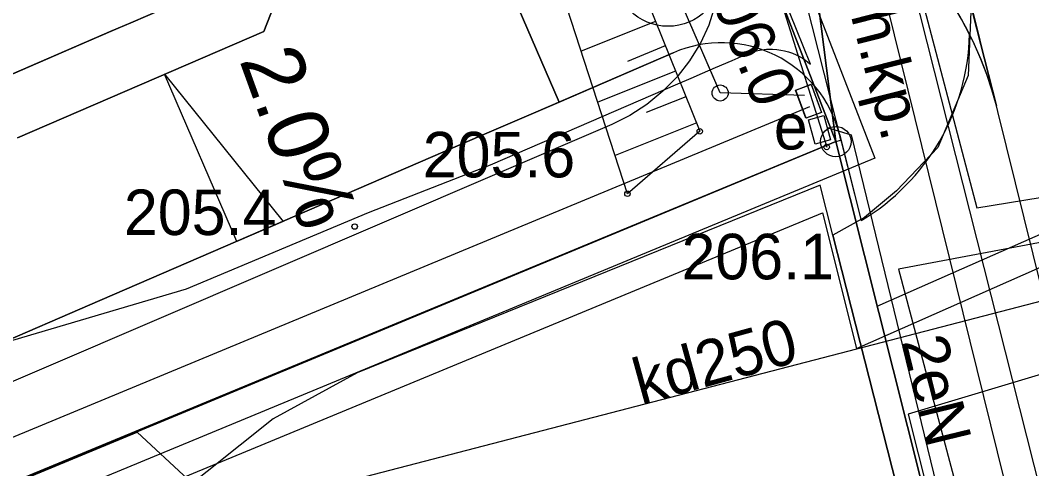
# Model space of a CAD drawing. Extents: x 6512606 to 6513006, y 6022524 to 6022728.
# Drawn here: x 6512842.35 to 6512859.01, y 6022578.56 to 6022585.95 of the extents above; entities that cross this region are included whole.
import ezdxf

# ---------------------------------------------------------------- set-up
doc = ezdxf.new("R2010")
doc.units = 0
for name, color, linetype in [('000 Inne (niezydentyfikowane)', 7, 'Continuous'), ('202-punkt graniczny', 7, 'Continuous'), ('216-obręb ewidencyjny', 7, 'Continuous'), ('217-kontur klasyfikacyjny', 7, 'Continuous'), ('218-kontur użytku gruntowego', 7, 'Continuous'), ('219-działka ewidencyjna', 7, 'Continuous'), ('4', 7, 'Continuous'), ('chodnik (powierzchnia)', 7, 'Continuous'), ('chodnik (powierzchnia)-Atr17', 7, 'Continuous'), ('Default', 7, 'Continuous'), ('E_OSW_KABLE', 7, 'Continuous'), ('E_OSW_LAMPA', 7, 'Continuous'), ('jezdnia (powierzchnia)', 7, 'Continuous'), ('kolor_chodnik', 7, 'Continuous'), ('kolor_kostka_bet', 7, 'Continuous'), ('kolor_sc_rowerowa', 7, 'Continuous'), ('maxp_inst_energ', 7, 'Continuous'), ('maxp_kan_deszczowa', 7, 'Continuous'), ('maxp_kraw_nawierzchni', 7, 'Continuous'), ('maxp_krawężnik', 7, 'Continuous'), ('maxp_obrzeże', 7, 'Continuous'), ('maxp_przechyłki', 7, 'Continuous'), ('maxp_ramka_2', 7, 'Continuous'), ('ogrodzenie trwałe', 7, 'Continuous'), ('pikieta naturalna', 7, 'Continuous'), ('pikieta naturalna-Atr2', 7, 'Continuous'), ('przewód elektroenergetyczny (linia)', 7, 'Continuous'), ('przewód elektroenergetyczny (linia)-Atr1', 7, 'Continuous'), ('przewód kanalizacyjny (linia)', 7, 'Continuous'), ('przewód kanalizacyjny (linia)-Atr1', 7, 'Continuous'), ('przewód telekomunikacyjny (linia)', 7, 'Continuous'), ('skarpa nieumocniona', 7, 'Continuous'), ('szafa elektroenergetyczna (powierzchnia)', 7, 'Continuous'), ('szafa elektroenergetyczna (powierzchnia)-Atr17', 7, 'Continuous'), ('urządzenie techniczne projektowane lub w budowie (sieć kanalizacyjna) - powierzchnia - ob. projektowany', 7, 'Continuous')]:
    doc.layers.add(name, color=color, linetype=linetype)

# ---------------------------------------------------------------- blocks, each defined once
blk = doc.blocks.new('202')
at = {"layer": 'Default'}
blk.add_circle((0, 0), 2.5, dxfattribs=at)
blk = doc.blocks.new('PW01')
at = {"layer": 'Default'}
blk.add_circle((0, 0), 0.45, dxfattribs=at)

msp = doc.modelspace()

# ---------------------------------------------------------------- linework, layer by layer
at = {"layer": '000 Inne (niezydentyfikowane)'}
for points in [[(6512852.81, 6022585.93), (6512851.59, 6022585.44)], [(6512852.97, 6022585.53), (6512852.35, 6022585.27)], [(6512853.14, 6022585.11), (6512851.86, 6022584.6)], [(6512853.31, 6022584.69), (6512852.66, 6022584.43)], [(6512853.49, 6022584.26), (6512852.15, 6022583.72)]]:
    msp.add_lwpolyline(points, dxfattribs=at)
at = {"layer": '216-obręb ewidencyjny'}
for points in [[(6512836.687, 6022675.173), (6512833.61, 6022675.02), (6512828.67, 6022670.98), (6512801.96, 6022670.34), (6512810.18, 6022663.28), (6512825.37, 6022649.66), (6512838.47, 6022634.29), (6512852.25, 6022608.25), (6512853.17, 6022604.51), (6512855.78, 6022583.95), (6512858.85, 6022571.74), (6512828.23, 6022562.62), (6512818.47, 6022559.72), (6512824.714, 6022553.406)], [(6512728.286, 6022540.131), (6512737.69, 6022552.74), (6512751.08, 6022569.37), (6512775.81, 6022564.08), (6512780.7, 6022581.02), (6512806.2, 6022572.11), (6512806.62, 6022563.51), (6512811.41, 6022558.95), (6512818.47, 6022559.72), (6512828.23, 6022562.62), (6512858.85, 6022571.74), (6512855.78, 6022583.95), (6512853.17, 6022604.51), (6512852.25, 6022608.25), (6512838.47, 6022634.29)]]:
    msp.add_lwpolyline(points, dxfattribs=at)
at = {"layer": '217-kontur klasyfikacyjny'}
for points in [[(6512855.78, 6022583.95), (6512848.55, 6022602.62)], [(6512825.22, 6022571.29), (6512855.78, 6022583.95)]]:
    msp.add_lwpolyline(points, dxfattribs=at)
at = {"layer": '218-kontur użytku gruntowego'}
for points in [[(6512855.78, 6022583.95), (6512853.17, 6022604.51)], [(6512853.17, 6022604.51), (6512855.78, 6022583.95)], [(6512848.55, 6022602.62), (6512855.78, 6022583.95)], [(6512855.78, 6022583.95), (6512848.55, 6022602.62)], [(6512825.22, 6022571.29), (6512855.78, 6022583.95)], [(6512855.78, 6022583.95), (6512825.22, 6022571.29)], [(6512858.85, 6022571.74), (6512855.78, 6022583.95)], [(6512855.78, 6022583.95), (6512858.85, 6022571.74)]]:
    msp.add_lwpolyline(points, dxfattribs=at)
at = {"layer": '219-działka ewidencyjna'}
for points in [[(6512855.78, 6022583.95), (6512853.17, 6022604.51)], [(6512855.78, 6022583.95), (6512848.55, 6022602.62)], [(6512825.22, 6022571.29), (6512855.78, 6022583.95)], [(6512858.85, 6022571.74), (6512855.78, 6022583.95)]]:
    msp.add_lwpolyline(points, dxfattribs=at)
at = {"layer": '4'}
for points in [[(6512855.78, 6022583.95), (6512853.17, 6022604.51)], [(6512855.78, 6022583.95), (6512848.55, 6022602.62)], [(6512825.22, 6022571.29), (6512855.78, 6022583.95)], [(6512858.85, 6022571.74), (6512855.78, 6022583.95)]]:
    msp.add_lwpolyline(points, dxfattribs=at)
at = {"layer": 'chodnik (powierzchnia)'}
msp.add_lwpolyline([(6512854.31, 6022590.11), (6512856.17, 6022582.76)], dxfattribs=at)
at = {"layer": 'E_OSW_KABLE'}
msp.add_lwpolyline([(6512855.264, 6022584.708), (6512853.876, 6022584.751), (6512849.902, 6022593.935)], dxfattribs=at)
for points in [[(6512855.117, 6022584.799), (6512855.373, 6022584.893), (6512855.544, 6022584.431), (6512855.289, 6022584.335)], [(6512855.119, 6022584.8), (6512855.374, 6022584.894), (6512855.545, 6022584.431), (6512855.291, 6022584.336)]]:
    msp.add_lwpolyline(points, close=True, dxfattribs=at)
at = {"layer": 'E_OSW_LAMPA'}
msp.add_line((6512853.372, 6022585.915), (6512853.823, 6022584.872), dxfattribs=at)
for centre, radius in [((6512853.018, 6022586.735), 0.885), ((6512853.876, 6022584.751), 0.132)]:
    msp.add_circle(centre, radius, dxfattribs=at)
at = {"layer": 'jezdnia (powierzchnia)'}
for points in [[(6512858.01, 6022586.22), (6512857.96, 6022585.04), (6512857.46, 6022583.85), (6512856.78, 6022583.14), (6512856.25, 6022582.7), (6512855.73, 6022582.41), (6512857.16, 6022576.8), (6512857.52, 6022576.87), (6512858.5, 6022576.75), (6512859.52, 6022576.13), (6512860.31, 6022575.24), (6512860.92, 6022574.44)], [(6512857.37, 6022576.01), (6512857.16, 6022576.8), (6512855.73, 6022582.41), (6512855.52, 6022583.23), (6512847.9, 6022580.14), (6512846.52, 6022579.38), (6512844.89, 6022578.08), (6512844.32, 6022577.3), (6512843.83, 6022576.12), (6512843.75, 6022575.7), (6512844.49, 6022572.59), (6512851.42, 6022574.26), (6512851.6, 6022573.59), (6512851.75, 6022573.46), (6512852.45, 6022574.3), (6512853.58, 6022574.86), (6512856.56, 6022575.84)]]:
    msp.add_lwpolyline(points, close=True, dxfattribs=at)
at = {"layer": 'kolor_chodnik'}
for p, q in [((6512849.637, 6022588.273), (6512851.225, 6022584.602)), ((6512851.225, 6022584.602), (6512853.105, 6022585.415))]:
    msp.add_line(p, q, dxfattribs=at)
msp.add_lwpolyline([(6512855.838, 6022584.07), (6512855.864, 6022583.971), (6512856.198, 6022582.648)], dxfattribs=at)
for centre, radius, start, end in [((6512852.619, 6022583.025), 6, 26.6607, 48.1262), ((6512854.308, 6022585.798), 3.674, 300.9641, 358.7377), ((6512853.9, 6022583.579), 2, 14.2012, 113.397)]:
    msp.add_arc(centre, radius, start, end, dxfattribs=at)
at = {"layer": 'kolor_kostka_bet'}
for p, q in [((6512858.424, 6022584.541), (6512854.975, 6022598.118)), ((6512844.176, 6022585.91), (6512848.334, 6022587.709)), ((6512846.363, 6022585.766), (6512846.884, 6022587.081)), ((6512841.472, 6022584.74), (6512843.862, 6022585.774)), ((6512842.307, 6022584.011), (6512846.363, 6022585.766)), ((6512843.862, 6022585.774), (6512844.176, 6022585.91)), ((6512849.922, 6022584.038), (6512843.498, 6022581.258)), ((6512855.864, 6022583.971), (6512855.838, 6022584.07)), ((6512843.498, 6022581.258), (6512839.274, 6022579.431))]:
    msp.add_line(p, q, dxfattribs=at)
for points in [[(6512846.884, 6022587.081), (6512844.176, 6022585.91), (6512843.862, 6022585.774)], [(6512843.862, 6022585.774), (6512841.909, 6022584.929), (6512841.472, 6022584.74)], [(6512853.105, 6022585.415), (6512851.225, 6022584.602), (6512849.922, 6022584.038)], [(6512773.05, 6022582.65), (6512780.7, 6022581.02), (6512806.2, 6022572.11), (6512806.62, 6022563.51), (6512855.78, 6022583.95)], [(6512773.05, 6022582.65), (6512780.7, 6022581.02), (6512806.2, 6022572.11), (6512806.62, 6022563.51), (6512855.78, 6022583.95)], [(6512855.78, 6022583.95), (6512855.864, 6022583.971)]]:
    msp.add_lwpolyline(points, dxfattribs=at)
for centre, radius, start in [((6512852.619, 6022583.025), 6, 14.633), ((6512853.9, 6022583.579), 2, 14.2012)]:
    msp.add_arc(centre, radius, start, 113.397, dxfattribs=at)
at = {"layer": 'kolor_sc_rowerowa'}
for p, q in [((6512851.225, 6022584.602), (6512849.637, 6022588.273)), ((6512846.884, 6022587.081), (6512846.363, 6022585.766)), ((6512846.363, 6022585.766), (6512842.307, 6022584.011)), ((6512849.922, 6022584.038), (6512851.225, 6022584.602)), ((6512843.498, 6022581.258), (6512849.922, 6022584.038)), ((6512839.274, 6022579.431), (6512843.498, 6022581.258))]:
    msp.add_line(p, q, dxfattribs=at)
at = {"layer": 'maxp_inst_energ'}
msp.add_line((6512828.214, 6022573.256), (6512855.354, 6022584.531), dxfattribs=at)
at = {"layer": 'maxp_kan_deszczowa'}
msp.add_lwpolyline([(6512841.985, 6022580.604), (6512845.089, 6022581.521), (6512848.087, 6022582.782), (6512848.087, 6022582.782), (6512850.094, 6022583.567), (6512851.554, 6022584.199), (6512852.937, 6022584.797), (6512852.937, 6022584.797), (6512853.18, 6022584.902), (6512853.396, 6022584.996), (6512853.585, 6022585.078), (6512853.801, 6022585.171), (6512854.071, 6022585.288), (6512854.322, 6022585.397), (6512854.372, 6022585.416), (6512854.423, 6022585.432), (6512854.475, 6022585.446), (6512854.521, 6022585.456), (6512854.559, 6022585.462), (6512854.638, 6022585.471), (6512854.686, 6022585.473), (6512854.738, 6022585.472), (6512854.81, 6022585.467), (6512854.875, 6022585.458), (6512854.936, 6022585.446), (6512855.002, 6022585.428), (6512855.066, 6022585.405), (6512855.126, 6022585.38), (6512855.192, 6022585.346), (6512855.23, 6022585.324), (6512855.282, 6022585.29), (6512855.321, 6022585.261), (6512855.362, 6022585.227), (6512855.131, 6022585.797), (6512853.495, 6022589.851)], dxfattribs=at)
at = {"layer": 'maxp_kraw_nawierzchni'}
msp.add_line((6512851.225, 6022584.602), (6512849.637, 6022588.273), dxfattribs=at)
at = {"layer": 'maxp_krawężnik'}
msp.add_line((6512846.884, 6022587.081), (6512841.909, 6022584.929), dxfattribs=at)
msp.add_arc((6512852.619, 6022583.025), 6, 14.633, 94.6616, dxfattribs=at)
at = {"layer": 'maxp_obrzeże'}
for p, q in [((6512854.975, 6022598.118), (6512858.424, 6022584.541)), ((6512846.363, 6022585.766), (6512846.884, 6022587.081)), ((6512846.363, 6022585.766), (6512842.307, 6022584.011)), ((6512853.105, 6022585.415), (6512843.498, 6022581.258)), ((6512855.838, 6022584.07), (6512856.198, 6022582.648)), ((6512843.498, 6022581.258), (6512839.274, 6022579.43))]:
    msp.add_line(p, q, dxfattribs=at)
for centre, radius, start, end in [((6512854.308, 6022585.798), 3.674, 300.9641, 358.7377), ((6512853.9, 6022583.579), 2, 14.2012, 113.397)]:
    msp.add_arc(centre, radius, start, end, dxfattribs=at)
at = {"layer": 'maxp_przechyłki'}
msp.add_lwpolyline([(6512844.727, 6022585.062), (6512846.68, 6022582.635), (6512845.92, 6022582.304)], close=True, dxfattribs=at)
at = {"layer": 'maxp_ramka_2'}
for p, q in [((6512848.827, 6022603.29), (6512856.423, 6022583.675)), ((6512855.903, 6022583.46), (6512856.462, 6022581.237)), ((6512855.56, 6022582.776), (6512856.122, 6022580.54)), ((6512856.462, 6022581.237), (6512860.068, 6022582.835)), ((6512856.122, 6022580.54), (6512860.654, 6022582.548))]:
    msp.add_line(p, q, dxfattribs=at)
for points in [[(6512856.423, 6022583.675), (6512826.273, 6022571.185), (6512822.563, 6022569.637), (6512806.155, 6022562.774)], [(6512805.691, 6022562.037), (6512822.756, 6022569.175), (6512826.465, 6022570.723), (6512855.56, 6022582.776)]]:
    msp.add_lwpolyline(points, dxfattribs=at)
at = {"layer": 'ogrodzenie trwałe'}
for points in [[(6512853.88, 6022589.44), (6512855.63, 6022583.86)], [(6512818.46, 6022560.27), (6512812.53, 6022565.9), (6512821.8, 6022569.74), (6512835.02, 6022575.32), (6512844.28, 6022579.16), (6512845.12, 6022578.38)]]:
    msp.add_lwpolyline(points, dxfattribs=at)
at = {"layer": 'przewód elektroenergetyczny (linia)'}
for points in [[(6512802.27, 6022673.66), (6512807.42, 6022670.09), (6512811.38, 6022666.87), (6512814.66, 6022663.43), (6512826.4, 6022651.65), (6512827.82, 6022650.09), (6512834.03, 6022642.46), (6512842.84, 6022631.19), (6512844.67, 6022626.95), (6512847.57, 6022619.87), (6512849.81, 6022612.67), (6512853.56, 6022600.08), (6512856.46, 6022588.83), (6512861.26, 6022569.82), (6512861.768, 6022567.654)], [(6512847.6, 6022616.23), (6512852.12, 6022605.09), (6512853.39, 6022601.13), (6512855.57, 6022592.48), (6512858.1, 6022582.86), (6512868.09, 6022584.49), (6512870.03, 6022584.23), (6512871.36, 6022584.34), (6512875.65, 6022585.56)], [(6512861.56, 6022603.29), (6512861.94, 6022603.39), (6512866.18, 6022583.61), (6512856.81, 6022581.85), (6512858.91, 6022573.95), (6512860.571, 6022567.194)], [(6512881.03, 6022586.32), (6512872.09, 6022583.77), (6512862.68, 6022581.17), (6512856.97, 6022579.46), (6512860.103, 6022567.013)], [(6512855.64, 6022584.18), (6512856.03, 6022584.06), (6512858.14, 6022575.39), (6512858.48, 6022574.45)], [(6512866.18, 6022583.61), (6512856.81, 6022581.85), (6512858.91, 6022573.95), (6512860.571, 6022567.194)]]:
    msp.add_lwpolyline(points, dxfattribs=at)
at = {"layer": 'przewód kanalizacyjny (linia)'}
msp.add_lwpolyline([(6512840.49, 6022576.47), (6512866.73, 6022583.29)], dxfattribs=at)
at = {"layer": 'przewód telekomunikacyjny (linia)'}
msp.add_lwpolyline([(6512836.6, 6022638.32), (6512844.42, 6022625.21), (6512848.91, 6022613.6), (6512851.86, 6022605.02), (6512853.91, 6022597.19), (6512860.14, 6022571.94), (6512860.33, 6022571.18)], dxfattribs=at)
at = {"layer": 'skarpa nieumocniona'}
msp.add_lwpolyline([(6512851.68, 6022588.74), (6512853.54, 6022584.12), (6512852.35, 6022583.09), (6512850.86, 6022587.69)], close=True, dxfattribs=at)
msp.add_lwpolyline([(6512851.68, 6022588.74), (6512853.54, 6022584.12), (6512852.35, 6022583.09), (6512850.86, 6022587.69)], close=True, dxfattribs=at)
at = {"layer": 'szafa elektroenergetyczna (powierzchnia)'}
msp.add_lwpolyline([(6512855.33, 6022584.31), (6512855.58, 6022584.38), (6512855.69, 6022583.98), (6512855.44, 6022583.91)], close=True, dxfattribs=at)
at = {"layer": 'urządzenie techniczne projektowane lub w budowie (sieć kanalizacyjna) - powierzchnia - ob. projektowany'}
msp.add_lwpolyline([(6512853.79, 6022586.19), (6512853.69, 6022585.87), (6512853.55, 6022585.57), (6512853.37, 6022585.28), (6512853.17, 6022585.02), (6512852.93, 6022584.78), (6512852.67, 6022584.56), (6512852.39, 6022584.38), (6512852.09, 6022584.23), (6512820.25, 6022570.56)], dxfattribs=at)

# ---------------------------------------------------------------- block references
at = {"layer": '202-punkt graniczny', "xscale": 0.1, "yscale": 0.10000000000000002}
msp.add_blockref('202', (6512855.78, 6022583.95), dxfattribs=at)
at = {"layer": 'pikieta naturalna', "xscale": 0.1, "yscale": 0.10000000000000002}
for p in [(6512853.54, 6022584.12), (6512855.63, 6022583.86), (6512852.35, 6022583.09), (6512847.86, 6022582.55)]:
    msp.add_blockref('PW01', p, dxfattribs=at)

# ---------------------------------------------------------------- texts
at = {"layer": 'chodnik (powierzchnia)-Atr17'}
msp.add_text('ch.kp.', height=0.75, rotation=284.201, dxfattribs=at).set_placement((6512855.9, 6022586.52))
at = {"layer": 'maxp_przechyłki'}
msp.add_text('2.0%', height=1, rotation=289.8994, dxfattribs=at).set_placement((6512845.956, 6022585.294))
at = {"layer": 'pikieta naturalna-Atr2'}
msp.add_text('206.0', height=0.75, rotation=291.93, dxfattribs=at).set_placement((6512853.53, 6022586.79))
for s, p in [('205.6', (6512848.98, 6022583.36)), ('205.4', (6512844.06, 6022582.41)), ('206.1', (6512853.24, 6022581.68))]:
    msp.add_text(s, height=0.75, dxfattribs=at).set_placement(p)
at = {"layer": 'przewód elektroenergetyczny (linia)-Atr1'}
msp.add_text('2eN', height=0.75, rotation=283.678, dxfattribs=at).set_placement((6512856.86, 6022580.66))
at = {"layer": 'przewód kanalizacyjny (linia)-Atr1'}
msp.add_text('kd250', height=0.75, rotation=15.379, dxfattribs=at).set_placement((6512852.57, 6022579.61))
at = {"layer": 'szafa elektroenergetyczna (powierzchnia)-Atr17'}
msp.add_text('e', height=0.75, dxfattribs=at).set_placement((6512854.76, 6022583.82))

doc.saveas('drawing.dxf')
